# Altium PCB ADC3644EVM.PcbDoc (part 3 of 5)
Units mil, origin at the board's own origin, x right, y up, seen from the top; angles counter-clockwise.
Board outline 3900 x 2716.54 mil, 10 copper layers (Top Layer, L2 GND, L3 PWR, L4 GND, L5 SIG, L6 GND, L7 GND, L8 PWR, L9 GND, Bottom Layer), stack 61.2 mil thick; 368 components, 252 nets, 1539 pads, 1019 vias.
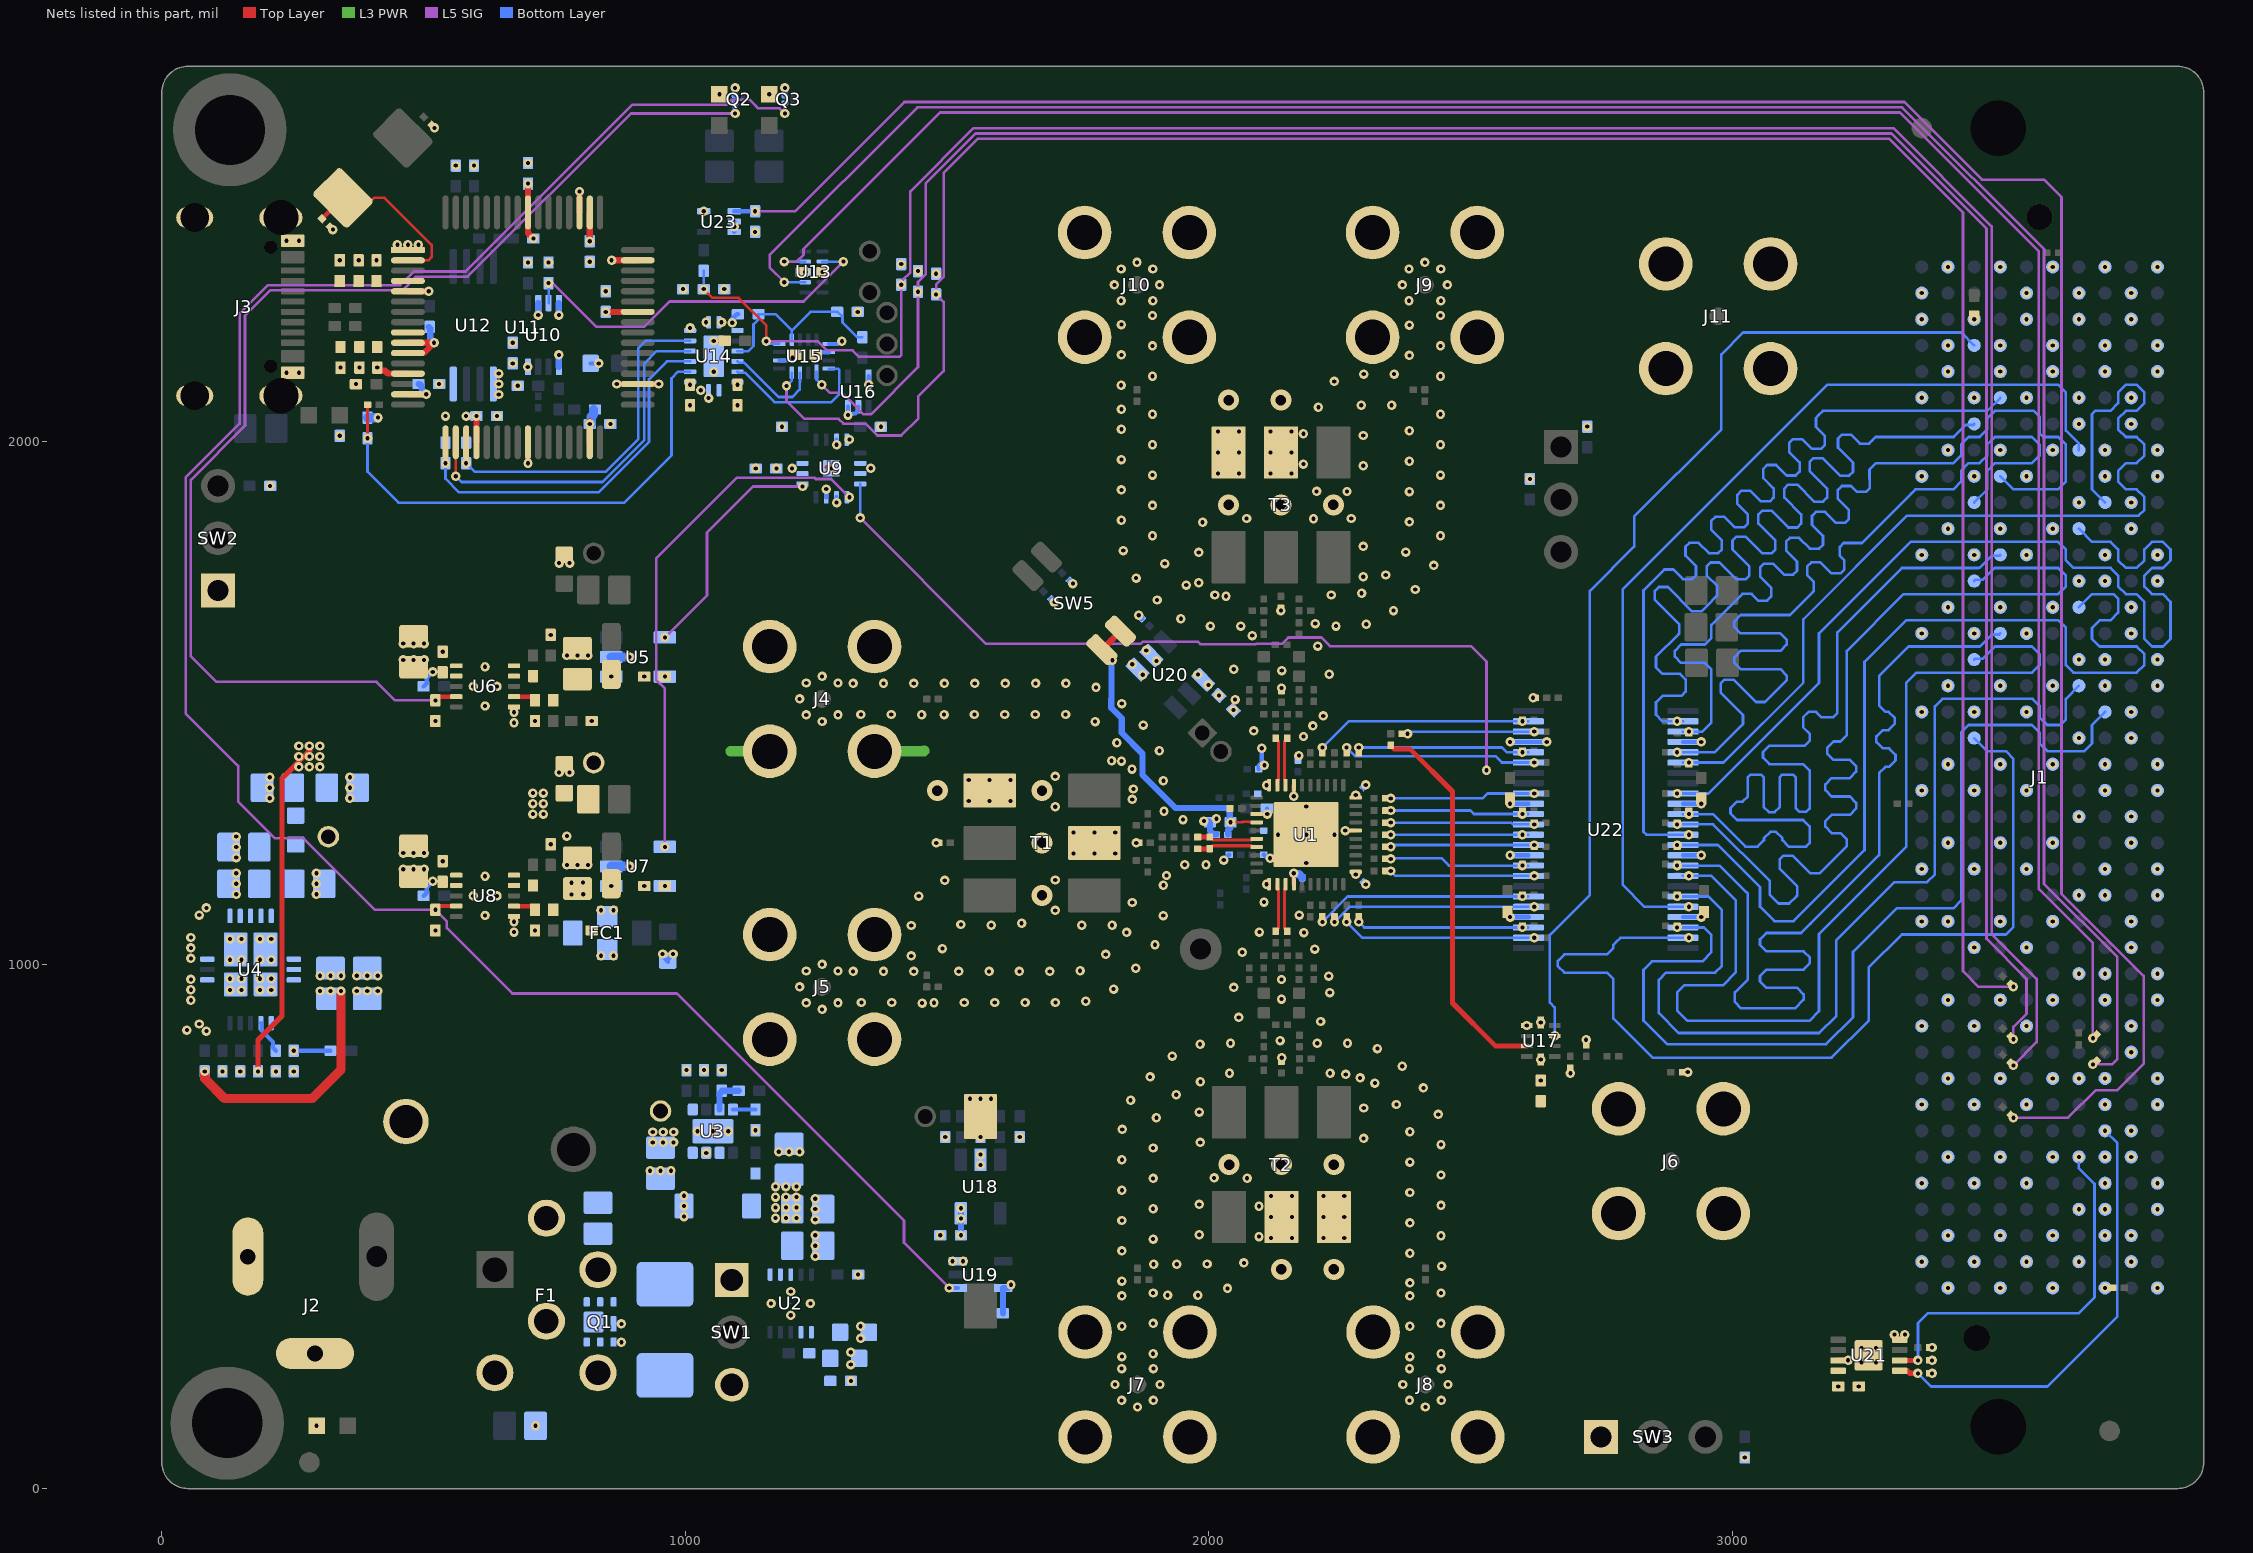
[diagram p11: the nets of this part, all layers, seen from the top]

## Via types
v1: diameter 18, hole 8, Top Layer to Bottom Layer, tented both sides, 1001 vias
v2: diameter 40, hole 20, Top Layer to Bottom Layer, tented both sides, 14 vias
v3: diameter 18, hole 8, Top Layer to Bottom Layer, tented bottom, 4 vias

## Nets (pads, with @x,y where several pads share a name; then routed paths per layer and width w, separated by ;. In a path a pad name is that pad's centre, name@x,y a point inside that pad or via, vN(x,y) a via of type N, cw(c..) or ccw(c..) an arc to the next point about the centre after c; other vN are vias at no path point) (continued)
1p8V_IOVDD: C27.2 C76.2 C77.2 FB3.2 PP4.1 U1.21 U1.30 U9.4 | length 1605.9
  Top Layer w8: v1(2280.18,1172.93) U1.21@2280.18,1177.93 ; U1.30@2280.18,1319.66 v1(2280.18,1324.66)
  L5 SIG w5: v1(1334.01,1853.77) 1574.46,1613.32 1869.32,1613.32 1873.21,1617.21 1978.99,1617.21 1983.54,1612.66 2089.32,1612.66 2089.98,1613.32 2139.48,1613.32 2151.58,1625.41 2214.74,1625.41 2231.24,1608.91 2500.47,1608.91 2530,1579.38 v1(2530,1371.94)
  Bottom Layer w5: v1(1334.01,1853.77) U9.4@1334.01,1918.77
  other v1: 708.74,1288.25 728.74,1288.25 708.74,1308.25 728.74,1308.25 708.74,1328.25 728.74,1328.25
1p8V_LVLSHIFT: C26.2 C46.2 C81.2 FC1.1 R27.1 R28.2 R56.1 R59.2 R60.2 R61.2 R70.2 R110.2 R120.2 R122.1 R130.2 R148.1 U7.1 U8.9 U8.10 U14.15 U16.5 U18.5 U19.5 U23.5 | length 158.5
  Top Layer w5: v1(2690.22,793.22) R70.2@2690.22,803.22
  Bottom Layer w5: v1(1099.53,2108.3) U14.15@1099.53,2113.3
  Bottom Layer w9: v1(1350,2108.49) U16.5@1350,2124.23
  Bottom Layer w12: C81.2@1526.23,483.68 v1(1526.21,535.51) ; R122.1@1606.46,334.78 1606.69,335.01 1606.69,382.82 U19.5@1606.92,383.05 1615.82,383.05 ccw(c1615.82,389.15) 1616.84,383.13 U19.5@1621.84,388.13 ; R130.2@1699.72,1697.94 1704.1,1693.55 1705.33,1693.55 v1(1704.72,1692.94) ; U19.5@1621.84,388.13 ccw(c1615.82,389.15) v1(1621.93,389.15) 1621.93,388.22 U19.5@1621.84,388.13
  other v1: 1526.26,483.65 1526.21,515.51 1496.21,671.34 782.74,1134.69 805,1135 858.46,1150.75 782.43,1156.95 804.69,1157.26 2722.46,2028.25 1329.09,2247.34 995.55,2290.74 1478.89,2320.15 1444.21,2325.15 1412.13,2338.64 1034.92,2439.49
2p3V: C14.2 C15.2 C18.2 C19.2 C24.2 C25.2 FB1.2 PP2.1 R12.2 R16.2 R26.2 U6.1 U6.2 U8.1 U8.2 | length 854.7
  Top Layer w8: v1(460.98,1182.66) 474.98,1168.66 C24.2@480.98,1168.66 ; v1(460.98,1582.66) 474.98,1568.66 C18.2@480.98,1568.66 ; v1(480.98,1182.66) C24.2@480.98,1168.66 ; v1(480.98,1582.66) C18.2@480.98,1568.66 ; v1(500.98,1182.66) 486.98,1168.66 C24.2@480.98,1168.66 ; v1(500.98,1582.66) 486.98,1568.66 C18.2@480.98,1568.66
  Top Layer w10: v1(183.89,796.75) 183.89,856.68 229.77,902.57 229.77,1356.43 282.4,1409.06
  Bottom Layer w8: R26.2@499.93,1132.05 500.25,1132.05 506.09,1137.89 506.09,1148.51 v1(517.4,1159.81) ; R16.2@499.93,1532.05 500.25,1532.05 506.09,1537.89 506.09,1548.51 v1(517.4,1559.81)
  other v1: 261.89,1378.18 281.89,1378.18 301.89,1378.18 261.89,1398.18 281.89,1398.18 301.89,1398.18 261.89,1418.18 281.89,1418.18 301.89,1418.18
3p3V_AUX: J1.D32
  other v1: 3661.42,783.27
3p3V_EEPROM: C88.2 U21.8
  other v1: 3201.8,194.99
3p3V_Utility: C7.2 C17.2 C23.2 C29.2 C30.2 C36.2 C37.2 C38.2 C39.2 C40.2 C41.2 C44.2 C45.2 C47.2 C55.2 C85.2 FB4.1 FB5.1 PP1.1 R5.2 R7.2 R10.2 R15.2 R24.2 R32.2 R33.2 R34.2 R35.1 R37.2 R38.1 R41.2 R47.2 R48.2 R49.2 R51.2 R52.2 R53.2 R54.2 R73.2 R131.2 U3.4 U3.5 U5.5 U7.5 U9.7 U9.10 U9.11 U10.8 U11.20 U11.31 U11.42 U11.50 U11.56 U12.8 U13.8@1261.85,2323.6 U14.1 U14.2 U14.8 U14.16 U15.14 U17.10 U20.4 | length 426.6
  Top Layer w11: v1(847.98,2247.34) U11.42@908.98,2247.34
  Top Layer w12: U11.20@600.91,1998.32 v1(600.91,2048.32) ; v1(699.33,2492.3) U11.56@699.33,2437.3 699.33,2397.82 v1(709.66,2387.5) ; U11.31@817.44,1998.32 v1@817.44,2038.32 ; v1(817.44,2382.3) U11.50@817.44,2437.3
  Bottom Layer w5: v1(1008.98,2108.3) U14.2@1008.98,2113.3 ; v1(1039.41,2227.47) U14.8@1044.41,2227.47
  Bottom Layer w8: v1(1249.02,2165.39) 1251.72,2165.39 1256.72,2170.39 U15.14@1274.02,2170.39
  Bottom Layer w9: U9.7@1269.05,1893.18 v1(1269.05,1908.92)
  Bottom Layer w12: v1(1865.91,1667.75) R131.2@1870.91,1662.75
  Bottom Layer w18: R52.2@392.95,2045.32 v1(412.95,2045.32) ; v1(817.44,2033.32) 819.41,2033.32 820.25,2034.16 820.25,2047 824.48,2051.23 R38.1@824.48,2060.88
  other v1: 3023.45,59.35 937.5,660.99 957.5,660.99 977.5,660.99 937.5,680.99 957.5,680.99 977.5,680.99 2633.64,779.36 251.89,796.75 1035.7,799.2 1069.29,799.2 2633.64,819.36 522.48,1065.91 960.83,1150.75 522.48,1465.91 2018.88,1514.78 1998.88,1534.78 960.83,1550.75 1978.88,1554.78 206.85,1915 1173.78,1948.29 1203.78,1948.29 1184.41,2027.82 1373.38,2027.82 541.85,2048.32 581.22,2048.32 1044.41,2082.55 1029.41,2097.55 679.65,2106.22 370.63,2109.54 529.61,2109.54 341.37,2140.87 699.03,2142.22 670.29,2148.91 1261.85,2323.6 699.33,2341.64 738.7,2341.64 340,2345.76 561.54,2526.67 596.22,2526.67
3p3VU_PG: R5.1 R9.2 U3.7 | length 70.4
  Bottom Layer w12: U3.7@1065.29,723.83 1065.29,753.86 1069.29,757.86 R5.1@1069.29,759.83 R9.2@1102.03,759.83
12V: C2.2 C3.2 C6.2 C9.2 C10.2 D1.1 D3.1 D4.1 D5.1 R6.2 R11.2 U2.6 U2.7 U2.8 U3.2 U4.18 | length 462.9
  Top Layer w18: v1(81.89,796.75) 81.89,783.11 120,745 287.48,745 342.26,799.78 v1(342.26,950.2)
  other v1: 295.33,119.85 1172.07,516.64 1192.07,516.64 1212.07,516.64 1172.07,536.64 1192.07,536.64 1212.07,536.64 1172.07,556.64 1192.07,556.64 1212.07,556.64 1172.07,576.64 1192.07,576.64 1212.07,576.64 302.26,950.2 322.26,950.2 372.26,950.2 392.26,950.2 412.26,950.2 1065,2663.11 1160,2663.11
12V_FMC: J1.C35 J1.C37 SW1.3
  other v1: 3711.42,533.27 3711.42,633.27
AIN_N: R85.2 U1.13 | length 93.3
  Top Layer w6.1: U1.13@2146.32,1154.31 2146.32,1146.44 2144,1144.11 2144,1070.85 2149.75,1065.1 R85.2@2149.75,1064.31
AIN_P: R77.2 U1.12 | length 93.3
  Top Layer w6.1: R77.2@2127.15,1064.31 2127.15,1065.1 2132.9,1070.85 2132.9,1144.11 2130.57,1146.44 U1.12@2130.57,1154.31
AVDD_PG: Q2.1@1095,2646.22 R15.1 U6.4 | length 2355.2
  Top Layer w8: v1(522.48,1505.28) 522.48,1506.52 528.32,1512.36 U6.4@562.48,1512.36
  L5 SIG w5: v1(522.48,1505.28) 445.42,1505.28 410,1540.7 104.24,1540.7 55.51,1589.43 55.51,1926.56 158.81,2029.87 158.81,2240.25 206.85,2288.29 459.46,2288.29 485.67,2314.49 584.28,2314.49 896.01,2626.22 v1(1095,2626.22)
  Bottom Layer w9.7: v1(1095,2626.22) Q2.1@1095,2646.22
BIN_N: R89.2 U1.38 | length 93.3
  Top Layer w6.1: U1.38@2146.32,1343.29 2146.32,1351.16 2144,1353.48 2144,1400.97 2144,1426.75 2149.75,1432.5 R89.2@2149.75,1433.29
BIN_P: R97.2 U1.39 | length 93.3
  Top Layer w6.1: R97.2@2127.15,1433.29 2127.15,1432.5 2132.9,1426.75 2132.9,1405.57 2132.9,1353.48 2130.57,1351.16 U1.39@2130.57,1343.29
CLK_N: C54.2 R66.1 U1.7 | length 115.8
  Top Layer w6.1: R66.1@2001.99,1221.75 2007.74,1227.5 2081,1227.5 2083.33,1225.18 U1.7@2091.2,1225.18
  Top Layer w9.7: C54.2@1978.2,1221.75 1994.35,1221.75 1994.9,1222.3 R66.1@2001.2,1222.3
CLK_P: C48.2 R66.2 U1.6 | length 116.3
  Top Layer w6.1: R66.2@2001.2,1244.35 2001.99,1244.35 2007.74,1238.6 2081,1238.6 2083.33,1240.92 U1.6@2091.2,1240.92
  Top Layer w9.7: C48.2@1978.2,1244.35 R66.2@2001.2,1244.35
CTRL: C86.2 C87.2 SW5.3 SW5.4 U1.4 | length 615.6
  Top Layer w5: v1(2041.2,1272.42) 2063.62,1272.42 2064.37,1273.17 2078.04,1273.17 2078.79,1272.42 U1.4@2091.2,1272.42
  Top Layer w12: v1(1815.55,1582.1) SW5.4@1795.55,1602.1 1806.13,1612.68 SW5.3@1830.91,1637.45
  Bottom Layer w12: v1(1815.55,1582.1) 1814.41,1580.95 1814.41,1576.71 1813.79,1576.09 1813.79,1507.94 1813.35,1507.51 1813.35,1490.94 1833.45,1470.85 1833.45,1443.35 1872.93,1403.87 1872.93,1363.32 1936.59,1299.66 2022.44,1299.66 2022.68,1299.91 2032.67,1299.91 2039.7,1292.88 2039.7,1273.92 v1(2041.2,1272.42) 2041.2,1262.58 2036.2,1257.58 C87.2@2036.2,1249.42
DA0: J1.D17 R153.2 U22.19 | length 1840.9
  Bottom Layer w5: v1(2893.99,1130.69) U22.19@2905.28,1130.69 2953.9,1130.69 2979.59,1105 2979.59,998.38 2966.47,985.26 2872.79,985.26 2859.02,971.49 2859.02,908.19 2897.21,870 3165.55,870 3198.27,902.72 3198.27,1047.27 3309.27,1158.27 3371.77,1158.27 3386.42,1172.91 3386.42,1493.62 3401.06,1508.27 3573.02,1508.27 3586.42,1494.86 3586.42,1472.91 3601.06,1458.27 3626.21,1458.27 3636.42,1468.48 3636.42,1477.06 3636.42,1508.27 J1.D17@3661.42,1533.27
DA1/FCLK: J1.D8 R155.2 U22.20 | length 1832
  Bottom Layer w5: U22.20@2905.28,1111 2832.27,1111 2790,1153.27 2790,1717.32 3180.95,2108.27 3561.42,2108.27 3621.77,2108.27 3636.42,2093.62 3636.42,2040.81 3636.42,2020.86 3661.42,1995.87 J1.D8@3661.42,1983.27
  other v1: 2916.56,1111
DA2: J1.H19 R159.2 U22.23 | length 1844
  Bottom Layer w5: v1(2916.56,1051.95) U22.23@2905.28,1051.95 2785.99,1051.95 2777.7,1043.66 2772.46,1038.42 2772.46,1032.51 2760.21,1020.26 2678.59,1020.26 2666.34,1008.01 2666.34,997.51 2678.59,985.26 2760.21,985.26 2772.46,973.01 2772.46,970.51 2772.46,897.82 2847.43,822.85 3189.41,822.85 3260,893.44 3260,994.85 3323.42,1058.27 3521.77,1058.27 3536.42,1072.91 3536.42,1393.62 3521.77,1408.27 3501.07,1408.27 3500.86,1408.47 3486.21,1408.47 J1.H19@3461.42,1433.27
DA3: J1.C18 R157.2 U22.22 | length 1843.5
  Bottom Layer w5: v1(2893.99,1071.63) U22.22@2905.28,1071.63 2945.36,1071.63 2959.61,1057.39 2959.61,1024.29 2942.32,1007 2846.16,1007 2830,990.84 2830,893.78 2875.21,848.57 3178.69,848.57 3230.11,899.99 3230.11,1024.95 3313.42,1108.27 3421.77,1108.27 3436.42,1122.91 3436.42,1443.62 3451.07,1458.27 3571.77,1458.27 3586.42,1443.62 3586.42,1422.91 3601.07,1408.27 3671.77,1408.27 3686.42,1422.92 3686.42,1458.27 J1.C18@3711.42,1483.27
DA4: J1.H16 R161.2 U22.17 | length 1833.6
  Bottom Layer w5: U22.17@2905.28,1170.06 2959.61,1170.06 3006.4,1123.27 3006.4,986.1 2981.27,960.98 2907.65,960.98 2894.31,947.64 2894.31,913.33 2914.2,893.44 3146.58,893.44 3165,911.86 3165,1059 3332,1226 3332,1539.2 3351.07,1558.27 3357.16,1558.27 3571.85,1558.27 3586.42,1572.83 3586.42,1593.62 3571.77,1608.27 3501.06,1608.27 3477.95,1585.16 3463.31,1585.16 J1.H16@3461.42,1583.27
  other v1: 2916.56,1170.06
DA5: J1.G15 R163.2 U22.16 | length 1841.2
  Bottom Layer w5: v1(2893.99,1189.74) U22.16@2905.28,1189.74 2975.15,1189.74 3025.84,1139.06 3026.16,1139.06 3029.09,1136.13 3029.09,972.39 3004.34,947.64 3004.34,929.41 3016.53,917.22 3119.26,917.22 3135.9,933.86 3135.9,941.36 3135.9,943.86 3123.65,956.11 3064.6,956.11 3052.35,968.36 3052.35,978.86 3064.6,991.11 3135.42,991.11 3147.67,1003.36 3147.67,1013.86 3135.42,1026.11 3064.6,1026.11 3052.35,1038.36 3052.35,1048.86 3064.6,1061.11 3131.02,1061.11 3149,1079.09 3279.94,1210.03 3279.94,1328.79 3279.94,1366.29 3292.19,1378.54 3298.84,1378.54 3311.09,1390.79 3311.09,1401.29 3298.84,1413.54 3286.93,1413.54 3274.68,1425.79 3274.68,1436.29 3286.93,1448.54 3297.83,1448.54 3310.08,1460.79 3310.08,1471.29 3297.83,1483.54 3292.19,1483.54 3279.94,1495.79 3279.94,1533.27 3279.94,1552.24 3335.97,1608.27 3472.36,1608.27 3495.18,1631.08 3509.23,1631.08 J1.G15@3511.42,1633.27
DA6: J1.D14 R165.2 U22.14 | length 1844.2
  Bottom Layer w5: v1(2893.99,1229.11) U22.14@2905.28,1229.11 2972.17,1229.11 3052.35,1148.93 3052.35,1111.31 3080.16,1083.49 3116.44,1083.49 3252.06,1219.12 3252.06,1578.78 3331.55,1658.27 3622.29,1658.27 3636.42,1644.14 3636.42,1593.63 3636.42,1572.92 3651.06,1558.27 3771.77,1558.27 3786.42,1572.91 3786.42,1593.62 3771.77,1608.27 3701.06,1608.27 3686.42,1622.92 3686.42,1635 3686.42,1643.62 3701.07,1658.27 3721.77,1658.27 3736.42,1672.91 3736.42,1699.75 3727.9,1708.27 3686.42,1708.27 J1.D14@3661.42,1683.27
DB0: J1.H7 R169.2 U22.2 | length 1828.7
  Bottom Layer w5: U22.2@2905.28,1465.33 2866.63,1465.33 2853.78,1478.18 2853.78,1501.41 2866.38,1514.01 2902.4,1514.01 2910.33,1521.95 2910.33,1545.54 2899.95,1555.92 2866.38,1555.92 2853.78,1568.52 2853.78,1588.78 2896.47,1631.47 2898.24,1633.24 2898.24,1650.56 2851.6,1697.21 2851.6,1714.53 2859.02,1721.96 2876.35,1721.96 2922.99,1675.31 2940.31,1675.31 2951.68,1686.68 2969.24,1704.24 2971.01,1706.01 2971.01,1723.34 2950.41,1743.94 2950.41,1761.27 2957.83,1768.69 2975.15,1768.69 3007.37,1736.48 3024.69,1736.48 3032.12,1743.9 3032.12,1761.23 2999.9,1793.44 2999.9,1810.76 3007.33,1818.19 3024.65,1818.19 3056.86,1785.98 3074.19,1785.98 3081.61,1793.4 3081.61,1810.73 3049.4,1842.94 3049.4,1860.26 3056.83,1867.69 3074.15,1867.69 3106.36,1835.47 3123.69,1835.47 3131.11,1842.9 3131.11,1860.22 3098.9,1892.44 3098.9,1909.76 3106.32,1917.18 3123.65,1917.18 3155.86,1884.97 3173.18,1884.97 3180.61,1892.4 3180.61,1909.72 3147.06,1943.26 3147.06,1960.59 3154.49,1968.01 3171.81,1968.01 3205.36,1934.47 3222.68,1934.47 3230.11,1941.89 3230.11,1959.22 3201.31,1988.01 3201.31,2005.34 3208.74,2012.76 3226.06,2012.76 3243.25,1995.57 3260.57,1995.57 3266.53,2001.53 3273.27,2008.27 3422.17,2008.27 3445.08,2031.18 3459.33,2031.18 J1.H7@3461.42,2033.27
  other v1: 2894.06,1465.33
DB1: J1.G9 R171.2 U22.3 | length 1828.6
  Bottom Layer w5: U22.3@2905.28,1445.65 2942.43,1445.65 2959.61,1462.82 2959.61,1562.22 2959.61,1564.72 2947.36,1576.97 2901.94,1576.97 2889.69,1589.22 2889.69,1599.72 2901.94,1611.97 2947.36,1611.97 2959.61,1624.22 2959.61,1635 2959.61,1649.49 2992.3,1682.18 3018.82,1708.7 3036.14,1708.7 3048.87,1695.97 3066.2,1695.97 3073.62,1703.39 3073.62,1720.72 3052.72,1741.62 3052.72,1758.94 3060.15,1766.37 3077.47,1766.37 3098.37,1745.47 3115.69,1745.47 3123.12,1752.89 3123.12,1770.22 3102.22,1791.12 3102.22,1808.44 3109.64,1815.86 3126.97,1815.86 3147.87,1794.96 3165.19,1794.96 3172.62,1802.39 3172.62,1819.71 3151.72,1840.61 3151.72,1857.94 3159.14,1865.36 3176.46,1865.36 3197.37,1844.46 3214.69,1844.46 3222.11,1851.89 3222.11,1869.21 3201.21,1890.11 3201.21,1907.43 3208.64,1914.86 3225.96,1914.86 3237.27,1903.55 3254.6,1903.55 3262.02,1910.97 3262.02,1928.3 3261.63,1928.69 3261.63,1946.02 3273.88,1958.27 3304.81,1958.27 3421.77,1958.27 3436.42,1972.91 3436.42,1993.62 3451.06,2008.27 3463.31,2008.27 3471.77,2008.27 3486.42,2022.91 3486.42,2043.62 3501.07,2058.27 3560.93,2058.27 3575.48,2058.27 3586.42,2047.33 3586.42,2015.4 3593.55,2008.27 3621.77,2008.27 3636.42,1993.62 3636.42,1922.92 3621.77,1908.27 3611.42,1908.27 3536.42,1908.27 J1.G9@3511.42,1933.27
  other v1: 2916.63,1445.65
DB2: J1.C10 R175.2 U22.6 | length 1828.3
  Bottom Layer w5: U22.6@2905.28,1386.59 2982.71,1386.59 3135,1538.88 3135,1660.07 3333.2,1858.27 3775.36,1858.27 3786.42,1869.32 3786.42,1893.62 3771.77,1908.27 3751.06,1908.27 3736.42,1922.92 3736.42,1943.62 3751.06,1958.27 3771.77,1958.27 3786.42,1972.91 3786.42,1993.62 3771.77,2008.27 3751.06,2008.27 3736.42,2022.91 3736.42,2043.62 3751.07,2058.27 3771.77,2058.27 3786.42,2072.91 3786.42,2093.62 3771.77,2108.27 3751.06,2108.27 3736.42,2093.62 3736.42,2072.91 3721.77,2058.27 3692.68,2058.27 3686.42,2052.01 3686.42,1908.27 J1.C10@3711.42,1883.27
  other v1: 2916.56,1386.59
DB3: J1.H10 R173.2 U22.5 | length 1839.9
  Bottom Layer w5: v1(2893.99,1406.28) U22.5@2905.28,1406.28 2966.06,1406.28 3018.14,1458.35 3019.91,1460.12 3019.91,1477.45 2977.27,1520.08 2977.27,1537.41 2984.69,1544.83 3002.02,1544.83 3044.66,1502.19 3061.98,1502.19 3065.86,1506.07 3103.33,1543.55 3103.33,1552.61 3091.08,1564.86 3015.58,1564.86 3003.33,1577.11 3003.33,1587.61 3015.58,1599.86 3091.08,1599.86 3103.33,1612.11 3103.33,1621.18 3091.08,1633.43 3015.58,1633.43 3003.33,1645.68 3003.33,1656.18 3015.58,1668.43 3109.38,1668.43 3153.61,1712.65 3155.38,1714.42 3155.38,1731.75 3142.9,1744.22 3142.9,1761.55 3150.32,1768.97 3167.65,1768.97 3188.79,1747.83 3206.11,1747.83 3213.54,1755.26 3213.54,1772.58 3204.87,1781.25 3204.87,1798.57 3212.3,1805.99 3229.62,1805.99 3246.95,1805.99 3341.74,1900.78 3349.22,1908.27 3361.42,1908.27 3421.77,1908.27 3436.42,1922.91 3436.42,1943.62 3451.06,1958.27 3461.42,1958.27 3471.77,1958.27 3486.42,1972.92 3486.42,1993.62 3501.06,2008.27 3571.77,2008.27 3586.42,1993.62 3586.42,1972.91 3571.77,1958.27 3501.06,1958.27 3486.42,1943.62 3486.42,1908.27 J1.H10@3461.42,1883.27
DB4: J1.D11 R177.2 U22.9 | length 1844.9
  Bottom Layer w5: v1(2893.99,1327.54) U22.9@2905.28,1327.54 2953.58,1327.54 3165,1538.95 3165,1633.25 3340.02,1808.27 3621.77,1808.27 3636.42,1793.62 3636.42,1772.91 3651.06,1758.27 3721.77,1758.27 3736.42,1743.62 3736.42,1722.91 3751.07,1708.27 3771.77,1708.27 3786.42,1693.62 3786.42,1622.91 3801.06,1608.27 3821.77,1608.27 3836.42,1622.91 3836.42,1693.62 3821.77,1708.27 3801.06,1708.27 3786.42,1722.92 3786.42,1736.48 3786.42,1743.62 3801.06,1758.27 3821.77,1758.27 3836.42,1772.91 3836.42,1793.62 3821.77,1808.27 3801.06,1808.27 3786.42,1793.62 3786.42,1772.91 3771.77,1758.27 3751.06,1758.27 3736.42,1772.92 3736.42,1793.62 3721.77,1808.27 3711.42,1808.27 3686.42,1808.27 J1.D11@3661.42,1833.27
DB5: J1.G12 R179.2 U22.11 | length 1827.3
  Bottom Layer w5: U22.11@2905.28,1288.17 2962.52,1288.17 3024.69,1226 3045.3,1226 3047.8,1226 3060.05,1238.25 3060.05,1242.11 3072.3,1254.36 3082.8,1254.36 3095.05,1242.11 3095.05,1238.25 3107.3,1226 3140.16,1226 3145.34,1231.18 3147.06,1232.9 3147.06,1264.69 3134.81,1276.94 3008.38,1276.94 2996.13,1289.19 2996.13,1299.69 3008.38,1311.94 3019.21,1311.94 3029.09,1321.81 3029.09,1358.52 3033.85,1363.29 3054.77,1363.29 3059.54,1358.52 3059.54,1301.81 3069.41,1291.94 3080.24,1291.94 3090.12,1301.81 3090.12,1358.52 3094.88,1363.29 3115.8,1363.29 3120.57,1358.52 3120.57,1299.45 3127.26,1292.75 3140.93,1292.75 3147.06,1298.89 3147.06,1371.45 3134.81,1383.7 3070.31,1383.7 3058.06,1395.95 3058.06,1406.45 3070.31,1418.7 3137.91,1418.7 3147.54,1428.33 3147.54,1441.15 3135,1453.7 3135,1473.2 3145.34,1483.54 3159.25,1483.54 3169.88,1472.91 3192.13,1472.91 3200,1480.79 3200,1635 3323.27,1758.27 3469.39,1758.27 3471.77,1758.27 3494.88,1781.38 3509.53,1781.38 J1.G12@3511.42,1783.27
  other v1: 2916.56,1288.17
DB6: J1.H13 R181.2 U22.12 | length 1842.7
  Bottom Layer w5: v1(2893.99,1268.48) U22.12@2905.28,1268.48 2963.08,1268.48 3071.16,1160.4 3071.16,1134.01 3087.85,1117.32 3108.1,1117.32 3121.88,1131.1 3123.65,1132.87 3123.65,1150.19 3089.76,1184.08 3089.76,1201.4 3097.19,1208.83 3114.51,1208.83 3148.4,1174.94 3165.72,1174.94 3218.28,1227.49 3218.28,1235.27 3218.28,1237.06 3218.28,1239.57 3206.03,1251.81 3189.42,1251.81 3177.17,1264.06 3177.17,1274.57 3189.42,1286.81 3223.95,1286.81 3236.2,1299.06 3236.2,1309.57 3223.95,1321.81 3189.42,1321.81 3177.17,1334.06 3177.17,1344.57 3189.42,1356.81 3223.95,1356.81 3236.2,1369.06 3236.2,1379.57 3223.95,1391.81 3193.03,1391.81 3180.78,1404.06 3180.78,1414.57 3193.03,1426.81 3206.03,1426.81 3218.28,1439.06 3218.28,1461.18 3218.28,1599.82 3326.72,1708.27 3621.77,1708.27 3636.42,1722.91 3636.42,1743.62 3621.77,1758.27 3500.4,1758.27 3477.62,1735.49 3463.64,1735.49 J1.H13@3461.42,1733.27
DC-DC_PG: R10.1 R23.2 U4.19 | length 70.2
  Bottom Layer w8: v1(251.89,836.12) R23.2@322.11,836.12
DCLK: J1.G6 R167.2 U22.13 | length 1836.4
  Bottom Layer w5: v1(2916.56,1248.8) U22.13@2905.28,1248.8 2835.28,1248.8 2830,1254.08 2830,1715.49 2843.18,1728.67 2869.69,1755.18 2887.02,1755.18 2905.34,1736.86 2922.67,1736.86 2930.09,1744.28 2930.09,1761.61 2910.11,1781.59 2910.11,1798.91 2917.53,1806.34 2934.86,1806.34 2954.84,1786.35 2972.17,1786.35 2979.59,1793.78 2979.59,1811.1 2959.61,1831.09 2959.61,1848.41 2967.03,1855.84 2984.36,1855.84 3004.34,1835.85 3021.66,1835.85 3029.09,1843.28 3029.09,1860.6 3009.1,1880.58 3009.1,1897.91 3016.53,1905.33 3033.85,1905.33 3053.84,1885.35 3071.16,1885.35 3078.59,1892.77 3078.59,1910.1 3058.6,1930.08 3058.6,1947.41 3066.03,1954.83 3083.35,1954.83 3103.33,1934.85 3120.66,1934.85 3128.08,1942.27 3128.08,1959.6 3108.1,1979.58 3108.1,1996.9 3115.52,2004.33 3132.85,2004.33 3151.5,1985.68 3168.82,1985.68 3176.25,1993.1 3176.25,2010.42 3159.25,2027.42 3159.25,2044.74 3164.43,2049.92 3172.78,2058.27 3486.42,2058.27 J1.G6@3511.42,2083.27
DCLKIN: R127.1 U17.8 | length 734.7
  Top Layer w9.7: R127.1@2347.23,1419.45 2347.23,1418.66 2353.16,1412.73 2383.41,1412.73 2465,1331.15 2465,927.49 2547.53,844.95 U17.8@2607.07,844.95
DUT_DA0: R99.2 R152.1 U22.30 | length 423.5
  Top Layer w5: v1(2216.66,1082.26) R99.2@2216.66,1092.26
  Bottom Layer w5: v1(2216.66,1082.26) 2216.66,1082.5 2264.85,1130.69 U22.30@2610,1130.69
  other v1: 2598.72,1130.69
DUT_DA1/FCLK: R100.2 R154.1 U22.29 | length 403.6
  Top Layer w5: v1(2239.76,1082.26) R100.2@2239.76,1092.26
  Bottom Layer w5: v1(2239.76,1082.26) 2239.76,1082.5 2268.26,1111 U22.29@2610,1111 v1(2621.28,1111)
DUT_DA2: R102.2 R158.1 U22.26 | length 381.1
  Top Layer w5: v1(2262.86,1082.26) R102.2@2262.86,1092.26
  Bottom Layer w5: v1(2262.86,1082.26) 2262.86,1082.03 2292.94,1051.95 U22.26@2610,1051.95 v1(2621.28,1051.95)
DUT_DA3: R103.2 R156.1 U22.27 | length 338.4
  Top Layer w5: v1(2285.96,1082.26) R103.2@2285.96,1092.26
  Bottom Layer w5: v1(2285.96,1082.26) 2296.59,1071.63 U22.27@2610,1071.63
  other v1: 2598.72,1071.63
DUT_DA4: R104.2 R160.1 U22.32 | length 288
  Top Layer w5: R104.2@2337.23,1179.5 v1(2347.23,1179.5)
  Bottom Layer w5: v1(2347.23,1179.5) 2356.67,1170.06 U22.32@2610,1170.06 ; U22.32@2607.4,1170.06 U22.32@2618.68,1170.06
  other v1: 2621.28,1170.06
DUT_DA5: R105.2 R162.1 U22.33 | length 279.2
  Top Layer w5: R105.2@2337.23,1202.6 v1(2347.23,1202.6)
  Bottom Layer w5: v1(2347.23,1202.6) 2348.56,1203.93 2444.32,1203.93 2458.51,1189.74 U22.33@2610,1189.74
  other v1: 2598.72,1189.74
DUT_DA6: R106.2 R164.1 U22.35 | length 285.5
  Top Layer w5: R106.2@2337.23,1225.7 v1(2347.23,1225.7)
  Bottom Layer w5: v1(2347.23,1225.7) 2350.74,1225.7 2354.16,1229.11 U22.35@2610,1229.11 v1(2621.28,1229.11)
DUT_DB0: R111.2 R168.1 U22.47 | length 424
  Top Layer w5: R111.2@2216.66,1405.33 v1(2216.66,1415.33)
  Bottom Layer w5: v1(2216.66,1415.33) 2266.66,1465.33 U22.47@2610,1465.33
  other v1: 2598.72,1465.33
DUT_DB1: R123.1 R170.1 U22.46 | length 244.3
  Top Layer w5: R123.1@2369.27,1441.5 v1(2379.27,1441.5)
  Bottom Layer w5: v1@2386.94,1445.65 U22.46@2610,1445.65 v1(2621.28,1445.65)
DUT_DB2: R113.2 R174.1 U22.43 | length 380.5
  Top Layer w5: R113.2@2262.86,1405.33 v1(2262.86,1415.33)
  Bottom Layer w5: v1(2262.86,1415.33) 2262.86,1415.1 2279.12,1398.83 2547.19,1398.83 2559.43,1386.59 U22.43@2610,1386.59 v1(2621.28,1386.59)
DUT_DB3: R114.2 R172.1 U22.44 | length 337.8
  Top Layer w5: R114.2@2285.96,1405.33 v1(2285.96,1415.33)
  Bottom Layer w5: v1(2285.96,1415.33) 2559.43,1415.33 2568.49,1406.28 U22.44@2610,1406.28
  other v1: 2598.72,1406.28
DUT_DB4: R115.2 R176.1 U22.40 | length 288
  Top Layer w5: R115.2@2337.23,1318.1 v1(2347.23,1318.1)
  Bottom Layer w5: v1(2347.23,1318.1) 2522.71,1318.1 2532.15,1327.54 U22.40@2610,1327.54 v1(2621.28,1327.54)
DUT_DB5: R116.2 R178.1 U22.38 | length 275.6
  Top Layer w5: R116.2@2337.23,1295 v1(2347.23,1295)
  Bottom Layer w5: v1(2347.23,1295) 2499.34,1295 2505.91,1288.42 2609.74,1288.42 U22.38@2610,1288.17
  other v1: 2598.72,1288.17
DUT_DB6: R117.2 R180.1 U22.37 | length 285.5
  Top Layer w5: R117.2@2337.23,1271.9 v1(2347.23,1271.9)
  Bottom Layer w5: v1(2347.23,1271.9) 2577.06,1271.9 2580.47,1268.48 U22.37@2610,1268.48 v1(2621.28,1268.48)
DUT_DCLK: R98.2 R166.1 U22.36 | length 272.8
  Top Layer w5: R98.2@2337.23,1248.8 v1(2347.23,1248.8)
  Bottom Layer w5: v1(2347.23,1248.8) 2580.47,1248.8 U22.36@2610,1248.8
  other v1: 2598.72,1248.8
EXTGND: F1.3 J2.2 J2.3 TP2.1
FMC_C\S\_DUT_LVLS: R60.1 R142.1 U15.4 | length 4447.5
  Top Layer w5: R142.1@3531.71,962.97 v3(3536.42,958.27)
  L5 SIG w5: v1(1193.15,2106.02) 1193.15,2077.4 1227.45,2043.1 1292.36,2043.1 1301.74,2033.72 1344.15,2033.72 1366.55,2011.32 1412.13,2011.32 1444.85,2044.05 1444.85,2086.22 1493.1,2134.47 1493.1,2266.58 v1(1478.89,2280.78) 1478.9,2299.65 1493.4,2314.15 1493.4,2512.94 1558.54,2578.09 3298.99,2578.09 3440,2437.08 3440,988.27 3470,958.27 v3(3536.42,958.27)
  Bottom Layer w5: v1(1193.15,2106.02) 1203.15,2116.02 U15.4@1203.15,2131.02
FMC_I2C_SCL: R139.1 U13.4 | length 4395.1
  Top Layer w10: v1(3688.23,860.08) R139.1@3694.85,866.7
  L5 SIG w5: v1(1188.98,2343.28) 1212.63,2343.28 1225.48,2356.13 1225.48,2367.09 1486.47,2628.09 2620,2628.09 ; 2790,2628.09 2620,2628.09 ; v1(3688.23,860.08) 3688.23,1041.77 3584.92,1145.08 3584.92,2362.87 3319.7,2628.09 2620,2628.09
  Bottom Layer w5: v1(1188.98,2343.28) U13.4@1228.98,2343.28
FMC_I2C_SDA: R140.1 U13.2 | length 4601.8
  Top Layer w10: v1(3688.23,810.08) R140.1@3694.85,816.7
  L5 SIG w5: v1(1188.98,2303.91) 1161.11,2331.78 1161.11,2356.13 1443.06,2638.09 2620,2638.09 ; 2790,2638.09 2620,2638.09 ; v1(3688.23,810.08) 3724.99,810.08 3734.92,820 3734.92,1015.08 3594.92,1155.08 3594.92,2367.01 3323.84,2638.09 2620,2638.09
  Bottom Layer w5: v1(1188.98,2303.91) U13.2@1228.98,2303.91
FMC_SCLK_DUT_LVLS: R59.1 R143.1 U15.1 | length 4368.2
  Top Layer w5: R143.1@3531.71,862.97 v3(3536.42,858.27)
  L5 SIG w5: v1(1260.39,2107.99) 1275.83,2092.55 1299.42,2092.55 1322.51,2069.47 1340.35,2051.62 1354.11,2051.62 1444.21,2141.73 1444.21,2145.58 v1(1444.21,2285.78) 1444.21,2304.65 1458.71,2319.15 1458.71,2492.4 1554.39,2588.09 3303.13,2588.09 3484.92,2406.3 3484.92,1050.11 3561.42,973.61 3561.42,906.6 3536.42,881.6 v3(3536.42,858.27)
  Bottom Layer w5: U15.1@1250.39,2132.99 1250.39,2117.99 v1(1260.39,2107.99)
FMC_SDI_DUT: R146.1 R147.2 U23.1 | length 4715
  Top Layer w5: R146.1@3531.71,712.97 v3(3536.42,708.27)
  L5 SIG w5: v1(1133.18,2439.49) 1209.54,2439.49 1418.14,2648.09 3327.99,2648.09 3476.07,2500 3595.03,2500 3628.21,2466.83 3628.21,1135.94 3785,979.14 3785,811.05 3734.92,760.97 3693.8,760.97 3641.1,708.27 v3(3536.42,708.27)
  Bottom Layer w8: U23.1@1093.18,2439.49 v1(1133.18,2439.49)
FMC_SDO_DUT_LVLS: R61.1 R62.1 R144.1 R148.2 R149.2 U15.8 | length 4687.6
  Top Layer w5: v1(1034.92,2290.74) 1051.42,2274.24 1101.36,2274.24 1154.53,2221.08 v1(1154.53,2191.14) ; R144.1@3531.71,812.97 v3(3536.42,808.27)
  L5 SIG w5: v1(1154.53,2191.14) 1253.15,2191.14 1270.56,2173.73 1319.06,2173.73 1331.33,2161.47 1409.2,2161.47 1412.13,2164.39 v1(1412.13,2299.27) 1414.61,2301.75 1414.61,2307.78 1429.71,2322.88 1429.71,2477.54 1550.25,2598.09 3307.28,2598.09 3494.92,2410.44 3494.92,1059.36 3580.66,973.61 3580.66,852.51 v3(3536.42,808.27)
  Bottom Layer w5: v1(1034.92,2290.74) R149.2@1034.92,2325.74 ; v1(1154.53,2191.14) 1157.23,2191.14 1162.23,2186.14 U15.8@1179.53,2186.14
FPGA_DCLKIN: J1.H4 U17.3 | length 1951.4
  Bottom Layer w5: v1(2660.22,864.64) 2660.22,919.21 2651.1,928.33 2651.1,1057.29 2727.5,1133.69 2727.5,1714.36 2812.17,1799.03 2812.17,1856.43 2978.68,2022.94 2978.68,2166.38 3020.21,2207.91 3436.77,2207.91 J1.H4@3461.42,2183.27
FTDI_C\S\_DUT_LVLS: U14.13 U15.3 | length 185.1
  Bottom Layer w5: U14.13@1099.53,2152.67 1101.75,2150.45 1112.4,2150.45 1178.02,2084.83 1204.35,2084.83 1218.15,2098.63 1218.15,2112.85 1218.9,2113.6 U15.3@1218.9,2131.02
FTDI_CSB_SHIFT: R53.1 U11.17 U14.4 | length 721.2
  Top Layer w5: v1(541.85,1958.32) U11.17@541.85,1998.32
  Bottom Layer w5: v1(541.85,1958.32) 541.85,1928.79 567.97,1902.67 834.37,1902.67 930.46,1998.75 930.46,2118.54 964.59,2152.67 U14.4@1008.98,2152.67
FTDI_I2C_SCL: R35.2 U10.3 U13.7 | length 727.2
  L5 SIG w5: v1(738.7,2302.27) 741.19,2299.78 748.78,2299.78 829.55,2219.01 921.46,2219.01 969.54,2267.09 1225.86,2267.09 1276.35,2317.59 1276.35,2317.78 v1(1301.85,2343.28)
  Bottom Layer w5: U10.3@738.7,2264.27 v1(738.7,2302.27) ; U13.7@1261.85,2343.28 v1(1301.85,2343.28)
FTDI_SCLK_DUT_LVLS: U14.14 U15.16 | length 292
  Bottom Layer w5: U14.14@1099.53,2132.99 1101.25,2131.27 1113.79,2131.27 1170.23,2074.83 1278.9,2074.83 1293.81,2089.74 1293.81,2136.39 1291.31,2138.89 U15.16@1274.02,2138.89
FTDI_SCLK_SHIFT: R36.2 R52.1 U14.3 | length 958.4
  Top Layer w5: v1(392.95,2005.95) R36.2@392.95,2070.17
  Bottom Layer w5: v1(392.95,2005.95) 392.95,1942.05 452.01,1882.99 883.27,1882.99 973.36,1973.08 973.36,2120.3 986.05,2132.99 U14.3@1008.98,2132.99
FTDI_SDI_SHIFT: R54.1 U11.19 U14.6 | length 680.4
  Top Layer w5: v1(581.22,1958.32) U11.19@581.22,1998.32
  Bottom Layer w5: v1(581.22,1958.32) 597.72,1941.82 847.76,1941.82 910,2004.06 910,2178.45 923.59,2192.04 U14.6@1008.98,2192.04
FTDI_SDIO_DUT_LVLS: R56.2 R57.2 R58.1 U14.12 U15.9 | length 369.5
  Bottom Layer w5: U14.12@1099.53,2172.36 1120.1,2172.36 1130.05,2182.31 1130.05,2223.58 1139.66,2233.18 R58.1@1139.66,2243.02 1171.83,2243.02 1203.15,2211.7 ; U15.9@1203.15,2194.01 1203.15,2211.7 ; R57.2@1337.95,2199.01 1328.11,2199.01 1299.97,2227.15 1299.97,2238.07 1290.71,2247.34 1288.74,2247.34 1238.79,2247.34 1203.15,2211.7
FTDI_SDO_SHIFT: U11.18 U14.5 | length 701.3
  Top Layer w5: v1@561.54,1938.32 U11.18@561.54,1998.32
  Bottom Layer w5: v1(561.54,1933.32) 572.5,1922.36 841.33,1922.36 921.46,2002.48 921.46,2148.91 944.9,2172.36 U14.5@1008.98,2172.36
GA0_FMC: J1.C34 R134.2 U21.1 | length 848.2
  Top Layer w10: U21.1@3319.06,224.99 3333.82,224.99 3338.82,219.99 v1(3354.06,219.99)
  Bottom Layer w5: v1(3354.06,219.99) 3379.05,195 3601.42,195 3735,328.58 3735,659.69 v1(3711.42,683.27)
GA1_FMC: J1.D35 R135.2 U21.2 | length 744.5
  Top Layer w10: U21.2@3319.06,244.68 v1(3354.06,244.68)
  Bottom Layer w5: v1(3354.06,244.68) 3354.06,315.9 3373.15,335 3661.42,335 3691.32,364.9 3691.32,581.79 3661.42,611.69 v1(3661.42,633.27)
GND: C2.1 C3.1 C4.1 C5.1 C6.1 C7.1 C8.1 C9.1 C10.1 C11.1 C12.1 C13.1 C14.1 C15.1 C16.2 C17.1 C18.1 C19.1 C20.1 C21.1 C22.1 C23.1 C24.1 C25.1 C26.1 C27.1 C28.1 C29.1 C30.1 C31.1 C32.1 C33.1 C34.1 C35.1 C36.1 C37.1 C38.1 C39.1 C40.1 C41.1 C42.1 C43.1 C44.1 C45.1 C46.1 C47.1 C50.2 C51.1 C55.1 C60.2 C61.1 C68.1 C69.2 C73.1 C74.1 C75.1 C76.1 C77.1 C78.1 C79.1 C80.1 C81.1 C82.1 C83.1 C84.1 C85.1 C86.1 C87.1 C88.1 C89.1 C90.1 C91.1 C92.1 C93.1 D3.2 FC1.2 J1.A1 J1.A4 J1.A5 J1.A8 J1.A9 J1.A12 J1.A13 J1.A16 J1.A17 J1.A20 J1.A21 J1.A24 J1.A25 J1.A28 J1.A29 J1.A32 J1.A33 J1.A36 J1.A37 J1.A40 J1.B2 J1.B3 J1.B6 J1.B7 J1.B10 J1.B11 J1.B14 J1.B15 J1.B18 J1.B19 J1.B22 J1.B23 J1.B26 J1.B27 J1.B30 J1.B31 J1.B34 J1.B35 J1.B38 J1.B39 J1.C1 J1.C4 J1.C5 J1.C8 J1.C9 J1.C12 J1.C13 J1.C16 J1.C17 J1.C20 J1.C21 J1.C24 J1.C25 J1.C28 J1.C29 J1.C32 J1.C33 J1.C36 J1.C38 J1.C40 J1.D2 J1.D3 J1.D6 J1.D7 J1.D10 J1.D13 J1.D16 J1.D19 J1.D22 J1.D25 J1.D28 J1.D37 J1.D39 J1.E1 J1.E4 J1.E5 J1.E8 J1.E11 J1.E14 J1.E17 J1.E20 J1.E23 J1.E26 J1.E29 J1.E32 J1.E35 J1.E38 J1.E40 J1.F2 J1.F3 J1.F6 J1.F9 J1.F12 J1.F15 J1.F18 J1.F21 J1.F24 J1.F27 J1.F30 J1.F33 J1.F36 J1.F39 J1.G1 J1.G4 J1.G5 J1.G8 J1.G11 J1.G14 J1.G17 J1.G20 J1.G23 J1.G26 J1.G29 J1.G32 J1.G35 J1.G38 J1.G40 J1.H3 J1.H6 J1.H9 J1.H12 J1.H15 J1.H18 J1.H21 J1.H24 J1.H27 J1.H30 J1.H33 J1.H36 J1.H39 J1.J1 J1.J4 J1.J5 J1.J8 J1.J11 J1.J14 J1.J17 J1.J20 J1.J23 J1.J26 J1.J29 J1.J32 J1.J35 J1.J38 J1.J40 J1.K2 J1.K3 J1.K6 J1.K9 J1.K12 J1.K15 J1.K18 J1.K21 J1.K24 J1.K26 J1.K30 J1.K33 J1.K36 J1.K39 J3.1 J3.2 J3.3 J3.4 J3.A1 J3.B1 J4.2 J4.3 J4.4 J4.5 J5.2 J5.3 J5.4 J5.5 J6.2 J6.3 J6.4 J6.5 J7.2 J7.3 J7.4 J7.5 J8.2 J8.3 J8.4 J8.5 J9.2 J9.3 J9.4 J9.5 J10.2 J10.3 J10.4 J10.5 J11.2 J11.3 J11.4 J11.5 Q1.4 Q1.7 Q2.2@1095,2660 Q3.2@1190,2660 R2.1 R3.1 R4.1 R8.1 R13.1 R14.1 R20.1 R22.1 R29.1 R31.1 R45.1 R46.1 R55.1 R58.2 R62.2 R71.1 R72.1 R101.1 R124.1 R132.1 R133.1 R134.1 R135.1 R136.1 R145.1 R147.1 R150.1 R182.1 SW2.3 SW3.3 SW4.2 T1.1 T1.5 T2.2 T2.3 T3.2 T3.3 U1.3 U1.11 U1.14 U1.26 U1.37 U1.40 U1.41 U2.11 U3.3 U3.9 U4.1 U4.2 U4.3 U4.5 U4.6 U4.7 U4.8 U4.9 U4.16 U4.17 U4.20 U4.25 U4.26 U4.28 U5.2 U6.6 U6.11 U7.2 U8.6 U8.11 U9.2 U9.3 U9.6 U9.15 U9.16 U9.17 U10.2 U10.4 U10.5 U11.1 U11.5 U11.10 U11.11 U11.13 U11.15 U11.25 U11.35 U11.47 U11.51 U12.5 U13.3@1228.98,2323.6 U14.7 U14.9 U14.10 U14.17 U15.6 U15.13 U16.2 U16.3 U17.5 U17.6 U18.2 U19.3 U20.1 U20.2 U21.4 U21.7 U21.9 U22.4 U22.10 U22.15 U22.21 U22.28 U22.34 U22.39 U22.45 U23.2 U23.3 | length 2231.7
  Top Layer w5: R72.1@2720.22,847.32 v1(2720.22,857.32) ; R71.1@2904.31,795.27 v1(2914.31,795.27)
  Top Layer w8: v1(460.98,1213.72) 474.98,1227.72 C24.1@480.98,1227.72 ; v1(460.98,1613.72) 474.98,1627.72 C18.1@480.98,1627.72 ; v1(480.98,1213.72) C24.1@480.98,1227.72 ; v1(480.98,1613.72) C18.1@480.98,1627.72 ; v1(500.98,1213.72) 486.98,1227.72 C24.1@480.98,1227.72 ; v1(500.98,1613.72) 486.98,1627.72 C18.1@480.98,1627.72 ; v1(758.74,1367.62) 758.74,1373.36 C27.1@768.74,1383.36 778.74,1373.36 v1(778.74,1367.62) ; v1(758.74,1767.62) 758.74,1773.36 C21.1@768.74,1783.36 778.74,1773.36 v1(778.74,1767.62) ; v1(773.72,1191.03) 787.72,1205.03 C26.1@793.72,1205.03 ; v1(773.72,1591.03) 787.72,1605.03 C20.1@793.72,1605.03 ; v1(793.72,1191.03) C26.1@793.72,1205.03 ; v1(793.72,1591.03) C20.1@793.72,1605.03 ; v1(813.72,1191.03) 799.72,1205.03 C26.1@793.72,1205.03 ; v1(813.72,1591.03) 799.72,1605.03 C20.1@793.72,1605.03 ; v1(1479.06,1233.05) C50.2@1484.06,1233.05 ; v1(1861.06,1233.05) C51.1@1866.06,1233.05 ; U1.3@2091.2,1288.17 v1(2111.2,1288.17) ; v1(2109.82,1154.31) U1.11@2114.82,1154.31 ; v1(2109.82,1343.29) U1.40@2114.82,1343.29 ; v1(2137.46,1676.83) C69.2@2137.46,1681.83 ; C68.1@2138.45,1523.99 v1(2138.45,1528.99) ; U1.14@2162.07,1154.31 v1(2162.07,1175.31) ; v1(2162.07,1322.29) U1.37@2162.07,1343.29 ; v1(2260.18,1256.67) U1.26@2280.18,1256.67 ; v1(2618.95,1510.29) R182.1@2622.95,1510.29 ; 1269.65,1950.47 1279.49,1950.47 1269.64,1950.48
  Top Layer w9: U14.17@1054.25,2192.04 R55.1@1075.16,2192.04
  Top Layer w9.7: C92.1@2570,1101.16 2573.41,1097.75 2573.41,1095.15 2575,1093.56 v1(2575,1091.32) ; v1(2575,1307.85) C89.1@2575,1317.69 ; v1(2940.28,1091.32) 2941.86,1092.9 2941.86,1095.15 2945.28,1098.56 C91.1@2945.28,1101.16 ; v1(2940.28,1307.85) C90.1@2940.28,1317.69
  Top Layer w10: U21.7@3201.8,244.68 3202.01,244.88 3220.36,244.88 v1(3220.57,245.09) ; v1(3309.06,294.05) U21.4@3319.06,284.05 v1(3329.06,294.05) ; R134.1@3376.1,219.99 v1(3381.1,219.99) ; R135.1@3376.1,244.68 v1(3381.1,244.68) ; R136.1@3376.1,269.36 v1(3381.1,269.36) ; v1(3461.42,2233.27) R150.1@3461.42,2238.58 ; v1(3711.42,383.27) R145.1@3726.08,383.27
  Top Layer w12: C42.1@321.7,2409.56 v1(326.7,2404.56) ; v1(411.37,2140.87) 411.37,2138.91 415.21,2135.06 426.33,2135.06 431.82,2129.57 469.65,2129.57 U11.13@470,2129.23 ; U11.15@470,2089.86 v1(505,2089.86) ; U11.11@470,2168.6 500.32,2168.6 v1(520,2188.28) U11.10@470,2188.28 ; U11.5@470,2286.71 v1(510,2286.71) ; C43.1@515.84,2603.7 v1(520.84,2598.7) ; v1(699.33,1958.32) U11.25@699.33,1998.32 ; U11.51@797.76,2437.3 v1(797.76,2477.3) ; v1(858.98,2345.76) U11.47@908.98,2345.76 ; v1(868.98,2109.54) U11.35@908.98,2109.54 v1(948.98,2109.54)
  L3 PWR w20: 1086.21,1408.05 J4.4@1161.11,1408.05 ; J4.5@1361.11,1408.05 1454.85,1408.05 1455.97,1409.17
  Bottom Layer w5: U14.7@1008.98,2211.73 v1(1008.98,2216.73) ; U14.9@1064.09,2227.47 v1(1069.09,2227.47)
  Bottom Layer w8: C35.1@818.86,2148.91 v1(834.61,2148.91) ; v1(956.48,1020.93) 956.48,1015.93 966.48,1005.93 966.48,1010.93 v1(976.48,1020.93) ; U23.3@1093.18,2400.12 v1(1093.18,2409.96) U23.2@1093.18,2419.8 ; U15.6@1179.53,2154.64 1196.82,2154.64 1201.82,2159.64 v1(1204.53,2159.64) ; U15.13@1274.02,2186.14 1291.31,2186.14 1296.31,2191.14 v1(1299.02,2191.14) ; v1(1288.74,1883.18) U9.6@1288.74,1893.18 ; v1(1288.74,1993.41) U9.15@1288.74,2003.41 ; U16.3@1310.63,2065.97 1310.63,2052.78 v1(1310.63,2050.22) 1312.54,2052.13 1319.1,2052.13 1320.32,2053.35 1324.98,2053.35 1330.32,2058.68 U16.2@1330.32,2065.97 ; v1(2028.18,1200.25) 2028.18,1200.67 2037.94,1210.43 C78.1@2038.72,1210.43 ; R132.1@2094.77,1374.15 2094.77,1380.45 2100.76,1386.44 v1(2100.76,1413.81) ; C79.1@2104.53,1210.43 2105.32,1210.43 2111.25,1204.5 2116.05,1204.5 v1(2116.62,1203.93) ; C82.1@2110.57,1298.92 2110.57,1289.07 2111.2,1289.07 v1(2111.2,1288.17) ; v1(2575,1209.43) U22.34@2610,1209.43 ; v1(2575,1307.85) U22.39@2610,1307.85 ; v1(2575,1425.96) U22.45@2610,1425.96 v1(2645,1425.96) ; U22.21@2905.28,1091.32 v1(2940.28,1091.32) ; U22.15@2905.28,1209.43 v1(2940.28,1209.43) ; U22.10@2905.28,1307.85 v1(2940.28,1307.85) ; U22.4@2905.28,1425.96 v1(2940.28,1425.96)
  Bottom Layer w9: v1(1089.53,2226.73) 1089.05,2227.2 1089.05,2233.76 1098.32,2243.02 R58.2@1100.29,2243.02
  Bottom Layer w9.7: Q2.2@1095,2660 v1(1095,2675) ; Q3.2@1190,2660 v1(1190,2675) ; v1(2575,1091.32) U22.28@2610,1091.32
  Bottom Layer w12: C37.1@490.24,2109.54 492.21,2109.54 496.06,2105.7 496.06,2099.89 505,2090.94 v1(505,2089.86) ; R46.1@510,2218.61 512.81,2215.81 512.81,2197.1 520,2189.9 v1(520,2188.28) v1@512,2188.28 ; v1(719.02,2241.27) U10.2@719.02,2264.27 ; U10.5@758.39,2142.22 v1(758.39,2165.22) ; v1(758.39,2241.27) U10.4@758.39,2264.27 ; v1@1313.15,2002.7 v1(1313.15,2003.55) ; R133.1@1735.07,1733.29 1739.46,1728.91 1740.69,1728.91 v1(1740.07,1728.29) ; v1(1990.19,1274.7) 1991.33,1273.56 2000.69,1273.56 C86.1@2001.83,1272.42 2001.83,1256.45 2008.86,1249.42 C87.1@2014.16,1249.42 ; C76.1@2295.77,1157.34 v1(2299.3,1153.81) ; C77.1@2295.77,1340.25 v1(2299.3,1343.79)
  Bottom Layer w15: v1@2162.07,1174.31 2162.64,1173.74 2171.8,1173.74 2177.82,1167.72 C73.1@2177.82,1166.93
  Bottom Layer w18: U7.2@858.46,1188.15 v1(893.46,1188.15) ; U5.2@858.46,1588.15 v1(893.46,1588.15)
  other v1: 713.73,119.85 1863.45,155.72 2413.45,155.72 1833.04,168.31 1893.85,168.31 2383.04,168.31 2443.85,168.31 3241.17,194.99 1820.45,198.72 1906.45,198.72 2370.45,198.72 2456.45,198.72 1316.31,205.62 1833.04,229.13 1893.85,229.13 2383.04,229.13 2443.85,229.13 1315.9,236.67 1833.73,251.91 2383.73,251.91 1893.17,257.52 2443.17,257.52 1315.9,260.14 877.82,279.42 1334.68,286.67 1334.68,310.14 1833.73,309.91 2383.73,309.91 877.82,314.42 1893.17,315.52 2443.17,315.52 1833.73,367.91 2383.73,367.91 1920.88,369 1978.88,369 1893.17,373.52 2443.17,373.52 2035.36,382.2 3411.42,383.27 3511.42,383.27 3611.42,383.27 3811.42,383.27 2383.73,392.76 1833.72,396.3 1329.96,408.64 2444.32,424.84 1894.32,428.42 1938.51,428.44 1996.5,428.81 2066.73,430.98 3361.42,433.27 3461.42,433.27 3561.42,433.27 3661.42,433.27 3761.42,433.27 1510.3,434.23 1530.3,434.23 1248.09,443.64 2383.73,449.44 1833.73,453.87 1248.09,463.64 1893.17,476.41 2118.45,478.72 2158.45,478.72 2218.45,478.72 2258.45,478.72 2095.58,481.3 2443.17,482.83 1248.09,483.64 1486.89,483.65 3411.42,483.27 3511.42,483.27 3611.42,483.27 3711.42,483.27 3761.42,483.27 1981.32,484.79 2383.73,507.44 1833.73,511.87 1248.09,513.64 2118.45,518.72 2158.45,518.72 2218.45,518.72 2258.45,518.72 997.3,519.36 1248.09,533.64 3661.42,533.27 3811.42,533.27 1893.17,534.41 997.3,539.36 2095.58,539.3 2443.17,540.83 1981.32,542.79 1248.09,553.64 2118.45,558.72 2158.45,558.72 2218.45,558.72 2258.45,558.72 997.3,559.36 2383.73,565.44 1833.73,569.87 3361.42,583.27 3461.42,583.27 3561.42,583.27 3711.42,583.27 3811.42,583.27 1893.17,592.41 2072.72,592.61 2009.73,593.35 2443.17,598.83 932.5,606.94 952.5,606.94 972.5,606.94 1563.61,617.87 2383.73,623.44 1833.73,627.87 3411.42,633.27 3511.42,633.27 3611.42,633.27 3761.42,633.27 1563.61,637.87 1039.7,641.15 1178.13,643.42 1198.13,643.42 1218.13,643.42 1893.17,650.41 2443.17,656.83 1983.29,661.04 2295.21,668.82 1563.61,671.34 1638.41,671.34 2383.69,681.44 3761.42,683.27 1133.88,684.46 1834.29,685.87 1899.57,708.05 2437.83,714.58 1981.32,719.01 2295.58,726.82 2358.06,733.47 3361.42,733.27 3461.42,733.27 3561.42,733.27 3711.42,733.27 3811.42,733.27 1850.33,741.61 1543.61,744.61 1563.61,744.61 1583.61,744.61 1937.39,752.02 2409.59,765.24 2316.86,774.3 1983.52,776.97 3411.42,783.27 3511.42,783.27 3611.42,783.27 3711.42,783.27 3811.42,783.27 2288.58,784.39 1887.47,786.16 2261.33,791.05 2039.16,793.35 2231.27,793.35 115.89,796.75 149.89,796.75 217.89,796.75 1002.1,799.2 2368.96,806.63 2138.87,822.85 1929.7,825.92 3761.42,833.27 2321.72,840.29 1983.09,848.57 2041.06,850.49 2206.62,850.49 2264.62,850.49 2135.87,855.52 85.27,873.58 47.89,875.49 3361.42,883.27 3461.42,883.27 3561.42,883.27 3761.42,883.27 2607.07,884.32 71.55,887.3 2633.64,890.23 2213.26,892 2056.72,899.9 1261.11,915.05 1230.7,927.64 1291.51,927.64 1452.07,927.18 1474.77,927.69 1336.09,928.33 1394.09,928.33 1532.76,928.33 1590.76,928.33 1648.76,928.33 1706.76,928.33 1764.71,930.73 55.51,932.48 3411.42,933.27 3511.42,933.27 3611.42,933.27 3711.42,933.27 3811.42,933.27 2138.45,934.79 2230.67,947.33 55.51,952.48 1817.9,953.86 2047.21,957.11 1218.11,958.05 55.51,972.48 2138.45,972.22 2228.88,978.84 302.26,979.25 322.26,979.25 342.26,979.25 372.26,979.25 392.26,979.25 412.26,979.25 3661.42,983.27 3711.42,983.27 3811.42,983.27 1320.3,987.77 1378.3,987.77 1436.3,987.77 1521.96,987.77 1579.96,987.77 1637.96,987.77 1695.96,987.77 1230.7,988.46 1291.51,988.46 1753.95,988.8 1860.11,993.63 1261.11,1001.05 55.51,1012.48 1431.39,1017.35 1802.68,1020.26 2063.68,1024.29 2202.05,1030.26 1490.83,1031.32 55.51,1032.48 3461.42,1033.27 3561.42,1033.27 3761.42,1033.27 1896.97,1038.42 55.51,1052.48 2181.3,1061.83 672.72,1062.68 1842.66,1062.28 2096.27,1062.84 712.72,1065.91 821.09,1065.91 1431.39,1075.35 1584.19,1075.92 1757.05,1075.92 1815.05,1075.92 1526.21,1077.28 1642.06,1079.77 672.72,1082.68 3361.42,1083.27 3411.42,1083.27 3511.42,1083.27 3611.42,1083.27 3761.42,1083.27 1912.59,1094.28 71.55,1095.3 2172.52,1095.34 1706.48,1104.31 85.27,1109.02 1853.44,1119.27 2105.13,1120.16 1445.8,1131.53 3661.42,1133.27 3711.42,1133.27 3811.42,1133.27 142.26,1135 295.33,1135 921.46,1150.75 1912.87,1152.28 142.26,1155 295.33,1155 1495.39,1161.6 1706.48,1162.31 1918.93,1170.82 142.26,1175 295.33,1175 3361.42,1183.27 3461.42,1183.27 3561.42,1183.27 3711.42,1183.27 3811.42,1183.27 1953.79,1191.31 1994.38,1191.25 536.41,1198.19 142.26,1205.06 1741.11,1213.05 1781.11,1213.05 1821.11,1213.05 142.26,1225.06 742.72,1230.47 3411.42,1233.27 3511.42,1233.27 3611.42,1233.27 3761.42,1233.27 142.26,1245.06 773.72,1246.01 1741.11,1253.05 1781.11,1253.05 1821.11,1253.05 1950.39,1277.59 2014.22,1279.37 3661.42,1283.27 3761.42,1283.27 1914.03,1293.68 1706.56,1302.08 1541.11,1313.05 1581.11,1313.05 1621.11,1313.05 1853.44,1316.16 206.27,1318.49 359.34,1318.49 3361.42,1333.27 3461.42,1333.27 3561.42,1333.27 3711.42,1333.27 3811.42,1333.27 1855.74,1336.13 206.27,1338.49 359.34,1338.49 1912.87,1351.66 1541.11,1353.05 1581.11,1353.05 1621.11,1353.05 206.27,1358.49 359.34,1358.49 1706.48,1360.08 1852.93,1374.15 2105.95,1381.33 3411.42,1383.27 3511.42,1383.27 3611.42,1383.27 3711.42,1383.27 3811.42,1383.27 1832.88,1389.44 1814.05,1390.18 2171.78,1399.92 1905.33,1409.17 1824.06,1424.46 3661.42,1433.27 3761.42,1433.27 2180.47,1436.31 2085.6,1447.04 2198.41,1456.49 1874.37,1458.21 672.72,1462.68 1782.46,1464.87 1261.11,1465.05 712.72,1465.91 821.09,1465.91 2218.11,1475.79 1230.7,1477.64 1291.51,1477.64 1335.23,1478.33 1393.23,1478.33 1451.23,1477.98 1494.04,1478.18 1552.04,1478.33 1610.04,1478.33 1668.04,1478.33 1726.04,1478.33 672.72,1482.68 3361.42,1483.27 3461.42,1483.27 3561.42,1483.27 3761.42,1483.27 2046.72,1486.94 1833.35,1499.23 2049.89,1506.87 1218.11,1508.05 1784.28,1530.13 3411.42,1533.27 3511.42,1533.27 3611.42,1533.27 3711.42,1533.27 3811.42,1533.27 1320.3,1537.77 1378.3,1537.77 1436.3,1537.77 1494.78,1537.77 1552.78,1537.77 1610.78,1537.77 1668.78,1537.77 1726.78,1537.77 1230.7,1538.46 1291.51,1538.46 921.46,1550.75 1261.11,1551.05 1873.6,1554.26 2229.69,1555.16 2139.08,1562.22 2047.21,1564.81 1853.6,1574.26 1900.05,1580.71 3661.42,1583.27 3711.42,1583.27 3811.42,1583.27 536.41,1598.19 1880.05,1600.71 2207.91,1608.91 2082.49,1629.16 742.72,1630.47 3361.42,1633.27 3461.42,1633.27 3561.42,1633.27 3761.42,1633.27 2002.77,1647.21 2060.77,1647.11 2242.62,1647.11 2300.51,1650.68 2202.84,1652 1946.45,1661.08 2352.34,1676.71 3411.42,1683.27 3511.42,1683.27 3611.42,1683.27 3761.42,1683.27 1900.91,1697 2032.53,1704.24 2011.27,1706.55 2233.6,1706.55 2291.51,1709.75 2394.04,1717.03 1956.43,1725.44 1980.51,1729.9 3661.42,1733.27 3711.42,1733.27 3811.42,1733.27 1860.76,1738.86 2294.59,1741.46 2337.73,1744.79 2429.31,1763.07 1915.47,1766.51 3361.42,1783.27 3461.42,1783.27 3561.42,1783.27 3711.42,1783.27 3811.42,1783.27 1980.33,1787.9 2375.81,1788.54 1836.08,1791.35 2294.59,1799.46 1892.18,1819.62 2442.18,1819.62 3411.42,1833.27 3511.42,1833.27 3611.42,1833.27 3761.42,1833.27 1987.91,1845.41 2382.74,1846.12 1832.74,1849.25 2071.74,1852.77 2199.55,1852.04 2271.74,1852.77 1892.18,1877.62 2442.18,1877.62 3661.42,1883.27 3761.42,1883.27 2205.63,1904.5 2263.63,1904.24 2382.74,1904.12 1832.74,1907.25 2612.93,1928.25 3361.42,1933.27 3461.42,1933.27 3561.42,1933.27 3711.42,1933.27 3811.42,1933.27 1892.18,1935.62 2442.18,1935.62 2017.46,1938.88 2057.46,1938.88 2117.46,1938.88 2157.46,1938.88 1134.41,1948.29 1354.11,1948.52 2294.59,1953.29 2180.33,1956.69 2382.74,1962.12 1832.74,1965.25 2017.46,1978.88 2057.46,1978.88 2117.46,1978.88 2157.46,1978.88 3411.42,1983.27 3511.42,1983.27 3611.42,1983.27 3711.42,1983.27 3811.42,1983.27 1892.18,1993.62 2442.18,1993.62 340,2010.63 2294.59,2011.29 2180.33,2014.69 2017.46,2018.88 2057.46,2018.88 2117.46,2018.88 2157.46,2018.88 2382.74,2020.12 1832.74,2023.25 856.81,2033.32 3661.42,2033.27 3761.42,2033.27 640.28,2048.32 1892.18,2051.62 2442.18,2051.62 1832.74,2061.25 2208.98,2065.12 1008.98,2068.93 1099.53,2068.93 2290.7,2069.16 2348.7,2069.16 3361.42,2083.27 3461.42,2083.27 3561.42,2083.27 3661.42,2083.27 3761.42,2083.27 643.39,2089.54 1832.07,2107.12 643.39,2109.54 2239.4,2114.51 1892.18,2124.43 2442.18,2124.43 2295.66,2128.6 2353.66,2128.6 643.39,2129.54 238.16,2131.19 262.16,2131.19 3411.42,2133.27 3511.42,2133.27 3611.42,2133.27 3711.42,2133.27 3811.42,2133.27 377.37,2140.87 2382.74,2164.14 1832.74,2165.11 1892.18,2182.43 2442.18,2182.43 3411.42,2183.27 3511.42,2183.27 3611.42,2183.27 3711.42,2183.27 3811.42,2183.27 670.29,2188.28 2382.74,2222.14 1832.74,2223.11 3361.42,2233.27 3561.42,2233.27 3661.42,2233.27 3761.42,2233.27 1892.18,2240.43 2442.18,2240.43 1832.06,2268.47 1892.87,2268.47 2382.06,2268.47 2442.87,2268.47 3361.42,2283.27 3561.42,2283.27 3661.42,2283.27 3761.42,2283.27 847.98,2286.71 1074.29,2290.74 1819.46,2298.88 1905.46,2298.88 2369.46,2298.88 2455.46,2298.88 1228.98,2323.6 1832.06,2329.28 1892.87,2329.28 2382.06,2329.28 2442.87,2329.28 3411.42,2333.27 3511.42,2333.27 3611.42,2333.27 3711.42,2333.27 3811.42,2333.27 1862.46,2341.88 2412.46,2341.88 817.44,2342.93 376,2345.76 410,2345.76 450,2375.45 470,2375.45 490,2375.45 238.16,2383.16 262.16,2383.16 1133.18,2400.12 699.33,2531.67
  other v2: 2138.45,418.72 2238.45,418.72 2038.45,618.72 2138.45,618.72 2238.45,618.72 1681.11,1133.05 1681.11,1233.05 1481.11,1333.05 1681.11,1333.05 2037.46,1878.88 2137.46,1878.88 2237.46,1878.88 2037.46,2078.88 2137.46,2078.88
IOVDD_PG: Q3.1@1190,2646.22 R24.1 U8.4 U19.1 | length 4092.9
  Top Layer w8: v1(522.48,1105.28) 522.48,1106.52 528.32,1112.36 U8.4@562.48,1112.36
  L5 SIG w5: v1(1190,2626.22) 1180,2636.22 1138.51,2636.22 1134.61,2640.12 1122.01,2652.72 1088.17,2652.72 1078.5,2643.05 898.7,2643.05 580.14,2324.49 481.52,2324.49 455.32,2298.29 202.71,2298.29 148.81,2244.39 148.81,2034.01 45.51,1930.7 45.51,1480.61 145.67,1380.45 145.67,1312.5 216.33,1241.84 270.16,1241.84 406.73,1105.28 v1(522.48,1105.28) 544.38,1083.37 544.38,1070.5 669.37,945.51 983.6,945.51 1417.41,511.71 1417.41,469.72 v1(1504.08,383.05)
  Bottom Layer w8: v1(1190,2626.22) Q3.1@1190,2646.22 ; v1(1504.08,383.05) U19.1@1520.3,383.05
ISENSE_AVDD: U5.4 U9.9 | length 457.3
  L5 SIG w5: v1(960.83,1625.55) 1041.3,1706.03 1041.3,1825.49 1129.58,1913.77 v1(1223.78,1913.77)
  Bottom Layer w5: v1(1223.78,1913.77) U9.9@1223.78,1918.77
ISENSE_IOVDD: U7.4 U9.5 | length 1011
  L5 SIG w5: v1(960.83,1225.55) 960.83,1527.72 944.33,1544.22 944.33,1776.67 1097.92,1930.27 1246.64,1930.27 1248.83,1928.07 1278.53,1928.07 v1(1313.42,1893.18)
  Bottom Layer w5: U9.5@1308.42,1893.18 v1(1313.42,1893.18)
NetC1_1: C1.1 D2.2 F1.2 Q1.3 SW1.1
NetC1_2: C1.2 D2.1 F1.4 Q1.1 Q1.2 Q1.5 Q1.6 Q1.8
NetC4_2: C4.2 R1.1 R4.2 U2.2
NetC5_2: C5.2 U2.1
NetC8_2: C8.2 U3.8 | length 43
  Bottom Layer w8: U3.8@1090.88,723.83 C8.2@1133.88,723.83
NetC11_2: C11.2 C12.2 C13.2 FB1.1 U4.10 U4.11 U4.12 U4.13 U4.14 U4.15 U4.27
NetC16_1: C16.1 U4.21 | length 64.7
  Bottom Layer w8: U4.21@189.27,888.94 190.19,888.02 190.19,874.88 212.1,852.96 212.1,841.91 C16.1@217.89,836.12
NetC20_2: C20.2 R17.1 R19.2 U5.1 U6.9 U6.10
  other v1: 858.46,1550.75
NetC22_2: C22.2 R21.2 U6.7 | length 44
  Top Layer w9: U6.7@672.72,1512.36 707.37,1512.36 712.72,1507.02 C22.2@712.72,1505.28
NetC28_2: C28.2 R30.2 U8.7 | length 44
  Top Layer w9: U8.7@672.72,1112.36 707.37,1112.36 712.72,1107.02 C28.2@712.72,1105.28
NetC31_2: C31.2 C32.2 FB4.2 U11.9
NetC33_2: C33.2 C34.2 FB5.2 U11.4
NetC42_2: C42.2 U11.2 Y1.1 | length 338.6
  Top Layer w5: Y1.1@346.11,2465.15 351.11,2460.15 400.47,2460.15 405.47,2465.15 425.62,2465.15 515.29,2375.49 515.29,2351.67 509.38,2345.76 U11.2@470,2345.76
  Top Layer w8: C42.2@306.11,2425.15 Y1.1@346.11,2465.15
